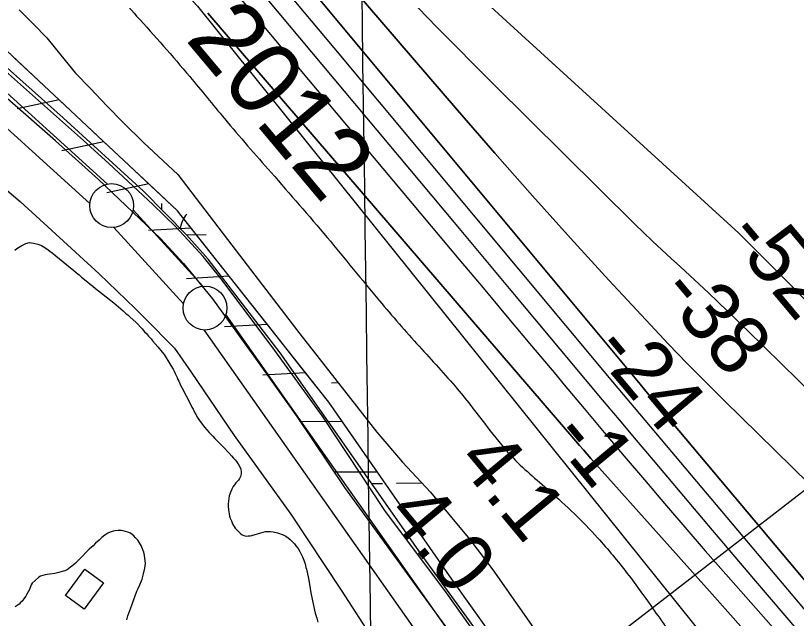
# Model space of a CAD drawing. Extents: x 3767014 to 3805179, y 361544 to 387384.
# Drawn here: x 3778598 to 3779487, y 381828 to 382515 of the extents above; entities that cross this region are included whole.
import ezdxf

# ---------------------------------------------------------------- set-up
doc = ezdxf.new("R2010")
doc.units = 0
for name, color, linetype in [('V-BLDG-OTLN', 7, 'Continuous'), ('V-FLOD-BASE', 7, 'Continuous'), ('V-GRID-MAJR', 7, 'Continuous'), ('V-LEVE-TOET', 7, 'Continuous'), ('V-RIVR-EDGE', 7, 'Continuous'), ('V-RIVR-IDEN', 7, 'Continuous'), ('V-RIVR-RANG', 7, 'Continuous'), ('V-RRAP-FSHR', 7, 'Continuous'), ('V-SITE-VEGE', 7, 'Continuous'), ('V-SURV-LINE', 7, 'Continuous'), ('V-TOPO-DPTH', 7, 'Continuous'), ('V-TOPO-MAJR', 7, 'Continuous'), ('V-TOPO-MINR', 7, 'Continuous'), ('V-TOPO-WATR', 7, 'Continuous'), ('V-WETL-SWMP', 7, 'Continuous')]:
    doc.layers.add(name, color=color, linetype=linetype)

msp = doc.modelspace()

# ---------------------------------------------------------------- linework, layer by layer
at = {"layer": 'V-BLDG-OTLN'}
msp.add_lwpolyline([(3778697.924, 381868.764), (3778675.963, 381838.749), (3778654.504, 381854.448), (3778676.467, 381884.464)], close=True, dxfattribs=at)
at = {"layer": 'V-FLOD-BASE'}
for points in [[(3778692.098, 382328.079), (3778643.187, 382372.197), (3778588.09, 382420.374), (3778515.771, 382484.163), (3778422.761, 382569.696), (3778344.896, 382643.025), (3778246.473, 382731.277)], [(3778692.098, 382328.079), (3778762.87, 382260.962), (3778789.22, 382232.479), (3778821.978, 382192.381), (3778878.031, 382114.78), (3778918.148, 382058.132), (3778972.438, 381977.367), (3779060.842, 381855.62), (3779132.377, 381757.961), (3779219.417, 381637.995), (3779266.709, 381582.32), (3779333.582, 381501.236), (3779412.295, 381404.55), (3779480.53, 381322.13), (3779548.774, 381238.814), (3779609.28, 381165.303), (3779648.831, 381119.88), (3779665.16, 381104.774), (3779773.337, 381026.358), (3779857.983, 380964.775), (3779951.271, 380892.497), (3779991.607, 380858.316), (3780033.308, 380822.351), (3780083.705, 380770.749)]]:
    msp.add_lwpolyline(points, dxfattribs=at)
at = {"layer": 'V-GRID-MAJR'}
msp.add_spline([(3779203.688, 367075.819), (3779120.863, 373133.445), (3779038.002, 379193.674), (3778955.14, 385253.903), (3778955.104, 385256.504)], degree=3, dxfattribs=at)
at = {"layer": 'V-LEVE-TOET'}
for points in [[(3778250.643, 382759.624), (3778379.499, 382638.087), (3778432.575, 382585.789), (3778534.504, 382496.902), (3778675.011, 382372.713), (3778703.947, 382346.241), (3778725.994, 382325.876)], [(3778314.358, 382577.321), (3778401.918, 382488.327), (3778454.988, 382436.713), (3778531.485, 382363.374), (3778603.096, 382303.001)], [(3778725.994, 382325.876), (3778754.088, 382299.649), (3778780.604, 382273.67), (3778811.592, 382240.57)], [(3778603.096, 382303.001), (3778693.111, 382220.604), (3778734.047, 382181.391), (3778745.423, 382169.797), (3778778.646, 382135.909), (3778797.842, 382108.634), (3778846.767, 382036.624), (3778911.184, 381947.211), (3778968.817, 381860.429), (3779005.427, 381803.607), (3779028.355, 381763.759), (3779050.305, 381731.106), (3779088.175, 381683.303), (3779173.349, 381590.048), (3779252.248, 381493.574), (3779342.061, 381386.855), (3779436.845, 381278.838)], [(3780122.202, 380758.347), (3780023.027, 380858.66), (3779982.219, 380894.594), (3779933.181, 380935.441), (3779861.303, 380988.323), (3779747.784, 381069.405), (3779669.919, 381129.952), (3779650.207, 381147.016), (3779629.983, 381169.53), (3779551.305, 381265.055), (3779458.846, 381375.434), (3779356.667, 381502.981), (3779247.187, 381633.631), (3779181.713, 381726.565), (3779088.588, 381857.385), (3779018.563, 381951.182), (3778947.489, 382058.599), (3778889.883, 382137.527), (3778830.456, 382216.891), (3778811.592, 382240.57)]]:
    msp.add_lwpolyline(points, dxfattribs=at)
at = {"layer": 'V-RIVR-EDGE'}
msp.add_spline([(3778646.24, 382647.92), (3778659.876, 382602.597), (3778687.287, 382567.754), (3778735.679, 382514.257), (3778796.164, 382445.365), (3778835.674, 382397.551), (3778888.899, 382335.956), (3778952.607, 382262.203), (3779012.275, 382190.077), (3779057.436, 382138.206), (3779100.988, 382089.574), (3779134.849, 382046.627), (3779162.264, 382013.401), (3779205.838, 381973.665), (3779260.7, 381920.153), (3779294.566, 381879.632), (3779325.194, 381837.502), (3779360.663, 381790.507), (3779412.312, 381745.899), (3779454.294, 381716.68), (3779488.994, 381685.863), (3779533.368, 381642.89), (3779576.119, 381597.495), (3779620.485, 381551.287), (3779676.969, 381499.388), (3779726.99, 381450.74), (3779776.179, 381392.389), (3779876.993, 381279.725), (3779935.05, 381210.029), (3779960.041, 381177.618), (3780000.375, 381136.273), (3780060.096, 381085.174), (3780089.114, 381046.283), (3780155.269, 380980.612), (3780221.433, 380918.984), (3780269.028, 380870.342), (3780345.672, 380794.939), (3780399.741, 380747.899), (3780525.62, 380632.747), (3780574.841, 380587.335), (3780617.604, 380546.793), (3780649.066, 380515.174), (3780673.232, 380476.295), (3780710.32, 380430.105), (3780715.929, 380409.064), (3780730.431, 380386.383), (3780746.557, 380366.934), (3780778.851, 380344.209), (3780832.137, 380307.684), (3780871.695, 380279.28), (3780938.666, 380216.842), (3780975.778, 380180.357), (3781018.547, 380142.24), (3781081.494, 380087.899), (3781142.025, 380037.607), (3781200.156, 379997.835), (3781279.276, 379942.646), (3781347.092, 379894.762), (3781401.179, 379855), (3781466.567, 379806.314), (3781540.856, 379760.032), (3781563.475, 379749.463), (3781591.761, 379741.305), (3781611.132, 379725.891), (3781641.814, 379705.597), (3781703.987, 379665.006), (3781768.578, 379621.175), (3781821.047, 379581.417), (3781840.409, 379561.959), (3781862.209, 379547.348), (3781884.029, 379540.824), (3781913.115, 379529.43), (3781965.635, 379509.89), (3782018.949, 379484.687), (3782023.776, 379474.162), (3782024.562, 379465.264), (3782031.018, 379459.587), (3782040.723, 379459.563), (3782056.888, 379455.479), (3782096.48, 379440.824), (3782142.534, 379422.918), (3782192.615, 379398.532), (3782256.437, 379370.877), (3782308.124, 379341.634), (3782355.768, 379312.402), (3782425.225, 379274.219), (3782483.37, 379240.108), (3782518.081, 379214.143), (3782612.541, 379148.401), (3782677.126, 379102.144), (3782722.345, 379073.726), (3782774.821, 379036.394), (3782813.562, 379004.757), (3782852.3, 378971.503), (3782891.856, 378942.291), (3782929.816, 378921.979), (3782948.387, 378909.802), (3782956.456, 378902.503), (3782965.324, 378891.159), (3782976.623, 378881.426), (3783009.747, 378867.595), (3783020.246, 378861.908), (3783062.243, 378838.351), (3783100.998, 378812.375), (3783151.876, 378783.135), (3783202.741, 378748.233), (3783247.956, 378718.198), (3783325.482, 378672.717), (3783407.843, 378619.945), (3783473.245, 378576.92), (3783515.225, 378546.893), (3783550.759, 378526.587), (3783593.566, 378503.836), (3783636.355, 378473.807), (3783701.749, 378427.547), (3783745.35, 378399.134), (3783781.695, 378379.634), (3783840.643, 378343.095), (3783916.53, 378288.722), (3783971.442, 378255.428), (3784058.669, 378208.305), (3784177.383, 378139.269), (3784249.255, 378096.228), (3784300.952, 378071.029), (3784367.999, 378039.322), (3784407.569, 378015.771), (3784474.592, 377974.36), (3784555.345, 377925.636), (3784594.113, 377904.513), (3784636.123, 377886.616), (3784690.236, 377857.368), (3784719.292, 377833.843), (3784772.601, 377806.214), (3784811.368, 377785.091), (3784863.85, 377750.185), (3784995.456, 377661.707), (3785050.364, 377626.795), (3785102.863, 377599.168), (3785153.772, 377582.059), (3785203.053, 377560.91), (3785266.865, 377529.211)], degree=3, dxfattribs=at)
at = {"layer": 'V-RIVR-RANG'}
msp.add_line((3779154.354, 381710.227), (3779787.615, 382199.083), dxfattribs=at)
at = {"layer": 'V-RRAP-FSHR'}
for p, q in [((3778647.232, 382418.815), (3778599.451, 382408.741)), ((3778698.347, 382370.991), (3778650.567, 382360.917)), ((3778749.462, 382323.168), (3778701.682, 382313.094)), ((3778797.832, 382272.817), (3778749.084, 382269.974)), ((3778841.251, 382217.912), (3778792.503, 382215.069)), ((3778884.671, 382163.007), (3778835.923, 382160.164)), ((3778928.09, 382108.101), (3778879.342, 382105.258)), ((3778970.17, 382052.202), (3778921.34, 382052.369)), ((3779010.123, 381994.725), (3778961.293, 381994.892))]:
    msp.add_line(p, q, dxfattribs=at)
for points in [[(3782184.756, 379271.949), (3781634.784, 379600.702), (3781303.145, 379780.78), (3781133.821, 379909.411), (3780890.404, 380113.256), (3780565.67, 380378.863), (3780204.676, 380695.617), (3779970.329, 380928.932), (3779684.372, 381135.741), (3779561.421, 381256.633), (3779323.818, 381551.992), (3779094.739, 381872.997), (3778954.725, 382074.421), (3778782.34, 382292.407), (3778544.366, 382515.056), (3778048.414, 382973.145), (3777558.565, 383445.969), (3777072.653, 383926.093), (3776661.747, 384415.936), (3776254.152, 384895.528), (3775977.183, 385214.815)], [(3777068.879, 384385.699), (3778804.838, 382525.57), (3779492.47, 381669.823), (3779587.876, 381548.643), (3779796.903, 381343.309), (3779998.867, 381129.354), (3780179.181, 380943.203), (3780223.637, 380900.07), (3780597.798, 380548.597), (3780675.78, 380460.512), (3780749.105, 380378.076), (3780977.321, 380170.04), (3781125.621, 380046.136), (3781247.143, 379955.707), (3781372.841, 379865.857), (3781588.295, 379714.948), (3781871.171, 379550.27), (3782261.845, 379357.404), (3782506.653, 379202.456), (3782967.84, 378875.243), (3783363.457, 378614.539), (3783723.393, 378389.37)], [(3778647.232, 382418.815), (3778596.116, 382466.639)], [(3778698.347, 382370.991), (3778647.231, 382418.815)], [(3778749.462, 382323.168), (3778698.346, 382370.992)], [(3778797.832, 382272.817), (3778782.34, 382292.407), (3778749.461, 382323.168)], [(3778841.251, 382217.912), (3778797.831, 382272.818)], [(3778884.671, 382163.007), (3778841.251, 382217.913)], [(3778928.09, 382108.101), (3778884.67, 382163.007)], [(3778970.17, 382052.202), (3778954.725, 382074.421), (3778928.09, 382108.102)], [(3779010.123, 381994.725), (3778970.17, 382052.203)], [(3779020.217, 381980.205), (3779010.123, 381994.726)]]:
    msp.add_lwpolyline(points, dxfattribs=at)
at = {"layer": 'V-SITE-VEGE'}
for points in [[(3778596.827, 382247.474), (3778599.034, 382249.407), (3778602.825, 382251.99), (3778604.881, 382253.124), (3778609.317, 382255.078), (3778613.759, 382256.237), (3778618.22, 382255.807), (3778623.004, 382254.583), (3778625.398, 382253.813), (3778627.317, 382252.877), (3778629.236, 382251.783), (3778633.24, 382249.278), (3778636.769, 382246.45), (3778639.493, 382244.57), (3778656.178, 382231.057), (3778664.2, 382224.459), (3778667.089, 382221.784), (3778670.137, 382219.429), (3778672.867, 382216.912), (3778680.084, 382211.257), (3778682.814, 382208.9), (3778685.7, 382206.7), (3778688.747, 382204.185), (3778709.6, 382187.695), (3778720.352, 382178.577), (3778723.885, 382175.274), (3778725.648, 382174.02), (3778727.899, 382171.815), (3778735.122, 382165.366), (3778742.038, 382158.118), (3778744.776, 382154.804), (3778746.865, 382152.758), (3778749.284, 382149.76), (3778752.182, 382146.608), (3778753.789, 382144.396), (3778759.907, 382137.617), (3778764.9, 382131.623), (3778766.837, 382128.78), (3778773.469, 382118.348), (3778774.441, 382116.447), (3778777.192, 382112.023), (3778778.329, 382109.805), (3778779.469, 382107.112), (3778781.743, 382102.523), (3778782.56, 382100.462), (3778783.692, 382098.566)], [(3778783.692, 382098.566), (3778785.974, 382093.337), (3778787.436, 382090.331), (3778796.683, 382072.925), (3778798.473, 382068.966), (3778799.931, 382066.435), (3778802.204, 382061.845), (3778803.337, 382060.107), (3778804.795, 382057.575), (3778808.027, 382052.676), (3778813.024, 382046.205), (3778818.176, 382040.212), (3778822.516, 382035.803), (3778824.769, 382033.28), (3778827.177, 382031.076), (3778830.235, 382027.769), (3778834.898, 382023.042), (3778840.85, 382016.74), (3778843.746, 382013.586), (3778846.16, 382010.748), (3778848.09, 382008.7), (3778850.346, 382005.859), (3778852.126, 382003.014), (3778853.427, 382000.321)], [(3778853.427, 382000.321), (3778854.404, 381998.105), (3778854.907, 381995.406), (3778854.774, 381992.861), (3778853.851, 381989.985), (3778852.921, 381987.591), (3778851.823, 381985.83), (3778848.833, 381982.616), (3778847.107, 381980.53), (3778845.695, 381978.449), (3778843.975, 381975.565), (3778843.049, 381972.694), (3778841.188, 381968.061), (3778840.295, 381962.005), (3778840.01, 381958.821), (3778840.043, 381955.64), (3778840.233, 381952.46), (3778841.585, 381944.677), (3778842.245, 381942.617), (3778843.549, 381939.289), (3778845.016, 381935.963), (3778847.768, 381931.218), (3778850.826, 381927.908), (3778853.877, 381925.076), (3778855.96, 381923.667), (3778857.877, 381922.891), (3778860.271, 381922.118), (3778862.817, 381922.463), (3778864.883, 381922.325), (3778866.948, 381922.663), (3778877.255, 381925.952), (3778882.334, 381927.118), (3778884.878, 381927.302), (3778887.741, 381927.333), (3778891.083, 381927.048), (3778896.029, 381925.825), (3778902.734, 381923.667), (3778905.618, 381921.787), (3778908.182, 381919.905), (3778910.429, 381918.018), (3778915.409, 381913.138), (3778917.181, 381911.088), (3778919.6, 381907.932), (3778921.703, 381904.61), (3778924.629, 381898.278), (3778926.1, 381894.632), (3778927.575, 381890.352), (3778928.572, 381886.225), (3778929.227, 381884.323), (3778931.226, 381875.594), (3778931.904, 381871.623), (3778932.422, 381867.492), (3778934.114, 381857.488), (3778936.969, 381843.037), (3778939.123, 381834.468), (3778940.932, 381828.76), (3778942.255, 381824.001)], [(3778724.427, 381826.704), (3778725.654, 381831.171), (3778730.141, 381843.467), (3778730.913, 381845.863), (3778736.025, 381859.28), (3778737.117, 381861.516), (3778739.292, 381866.63), (3778741.772, 381873.02), (3778743.617, 381879.242), (3778744.983, 381885.621), (3778745.434, 381888.331), (3778745.567, 381890.876), (3778745.372, 381894.374), (3778744.52, 381899.775), (3778743.685, 381903.906), (3778742.861, 381906.441), (3778741.071, 381910.4), (3778738.966, 381914.197), (3778736.865, 381917.357), (3778734.448, 381920.195), (3778732.519, 381922.245), (3778731.073, 381923.661), (3778728.507, 381925.545), (3778725.793, 381926.47), (3778722.922, 381927.236), (3778720.208, 381928.162), (3778718.138, 381928.301), (3778714.316, 381928.58), (3778711.14, 381928.23), (3778708.918, 381927.73), (3778705.588, 381926.581), (3778702.737, 381925.281), (3778699.579, 381923.179), (3778695.946, 381920.437), (3778692.794, 381917.541), (3778688.694, 381914), (3778686.017, 381911.108), (3778681.763, 381907.088), (3778670.11, 381895.355), (3778665.856, 381891.335), (3778663.02, 381888.761), (3778660.337, 381886.506), (3778656.389, 381883.759), (3778653.695, 381882.619), (3778651.793, 381881.963), (3778647.193, 381880.642), (3778642.274, 381879.479), (3778636.713, 381878.627), (3778633.693, 381878.439), (3778631.469, 381878.097), (3778626.238, 381876.292), (3778624.18, 381875.156), (3778619.922, 381871.615), (3778616.772, 381868.399), (3778615.359, 381866.636), (3778613.61, 381861.066)], [(3778613.61, 381861.066), (3778610.513, 381855.784), (3778609.485, 381853.672), (3778607.929, 381851.821), (3778605.082, 381847.854), (3778603.524, 381846.263), (3778601.703, 381844.667), (3778599.62, 381843.072), (3778597.271, 381841.472)]]:
    msp.add_lwpolyline(points, dxfattribs=at)
at = {"layer": 'V-SURV-LINE'}
for points in [[(3778143.366, 382830.007), (3778702.45, 382322.94)], [(3778682.288, 382300.726), (3778123.204, 382807.792)], [(3778731.723, 382293.74), (3778811.15, 382206.594)], [(3778788.982, 382186.381), (3778709.554, 382273.527)], [(3778837.291, 382174.017), (3779169.048, 381702.633)], [(3779144.516, 381685.364), (3778812.759, 382156.75)]]:
    msp.add_lwpolyline(points, dxfattribs=at)
for centre in [(3778707.175, 382298.405), (3778813.53, 382181.716)]:
    msp.add_circle(centre, 25, dxfattribs=at)
at = {"layer": 'V-TOPO-DPTH'}
for points in [[(3780033.44, 381447.279), (3779909.446, 381577.894), (3779904.885, 381582.669), (3779900.304, 381587.425), (3779895.694, 381592.152), (3779891.063, 381596.86), (3779845.629, 381642.766), (3779818.205, 381670.35), (3779790.697, 381697.851), (3779763.065, 381725.227), (3779735.35, 381752.519), (3779404.858, 382076.499), (3779383.577, 382097.655), (3779362.498, 382119.007), (3779341.72, 382140.652), (3779321.143, 382162.494), (3779273.749, 382213.512), (3779229.91, 382261.263), (3779186.451, 382309.353), (3779143.559, 382357.95), (3779101.046, 382406.885), (3778795.842, 382762.398)], [(3780033.44, 381447.279), (3779909.446, 381577.894), (3779904.885, 381582.669), (3779900.304, 381587.425), (3779895.694, 381592.152), (3779891.063, 381596.86), (3779845.629, 381642.766), (3779818.205, 381670.35), (3779790.697, 381697.851), (3779763.065, 381725.227), (3779735.35, 381752.519), (3779404.858, 382076.499), (3779383.577, 382097.655), (3779362.498, 382119.007), (3779341.72, 382140.652), (3779321.143, 382162.494), (3779273.749, 382213.512), (3779229.91, 382261.263), (3779186.451, 382309.353), (3779143.559, 382357.95), (3779101.046, 382406.885), (3778795.842, 382762.398)], [(3778720.082, 382730.103), (3778909.421, 382503.635), (3778972.04, 382428.742), (3779034.665, 382353.854), (3779097.296, 382278.972), (3779159.933, 382204.095), (3779246.656, 382100.433), (3779265.952, 382077.403), (3779285.271, 382054.393), (3779304.623, 382031.411), (3779323.999, 382008.449), (3779387.171, 381933.693), (3779438.344, 381873.534), (3779489.775, 381813.599), (3779541.593, 381753.998), (3779593.67, 381694.62), (3779748.837, 381518.851), (3779764.073, 381501.736), (3779779.401, 381484.707), (3779794.87, 381467.804), (3779810.433, 381450.987), (3780144.803, 381092.655)], [(3778720.082, 382730.103), (3778909.421, 382503.635), (3778972.04, 382428.742), (3779034.665, 382353.854), (3779097.296, 382278.972), (3779159.933, 382204.095), (3779246.656, 382100.433), (3779265.952, 382077.403), (3779285.271, 382054.393), (3779304.623, 382031.411), (3779323.999, 382008.449), (3779387.171, 381933.693), (3779438.344, 381873.534), (3779489.775, 381813.599), (3779541.593, 381753.998), (3779593.67, 381694.62), (3779748.837, 381518.851), (3779764.073, 381501.736), (3779779.401, 381484.707), (3779794.87, 381467.804), (3779810.433, 381450.987), (3780144.803, 381092.655)], [(3780425.097, 380890.853), (3779950.523, 381358.07), (3779925.981, 381382.495), (3779901.617, 381407.093), (3779877.52, 381431.954), (3779853.601, 381456.989), (3779813.295, 381499.634), (3779809.684, 381503.497), (3779806.1, 381507.385), (3779802.559, 381511.312), (3779799.046, 381515.264), (3779773.24, 381544.609), (3779756.908, 381563.307), (3779740.659, 381582.076), (3779724.534, 381600.952), (3779708.492, 381619.9), (3779329.372, 382070.73), (3779324.309, 382076.759), (3779319.252, 382082.794), (3779314.203, 382088.835), (3779309.16, 382094.881), (3778809.915, 382694.298)], [(3778809.915, 382694.298), (3779309.16, 382094.881), (3779314.203, 382088.835), (3779319.252, 382082.794), (3779324.309, 382076.759), (3779329.372, 382070.73), (3779708.492, 381619.9), (3779724.534, 381600.952), (3779740.659, 381582.076), (3779756.908, 381563.307), (3779773.24, 381544.609), (3779799.046, 381515.264), (3779802.559, 381511.312), (3779806.1, 381507.385), (3779809.684, 381503.497), (3779813.295, 381499.634), (3779853.601, 381456.989), (3779877.52, 381431.954), (3779901.617, 381407.093), (3779925.981, 381382.495), (3779950.523, 381358.07), (3780425.097, 380890.853)], [(3779014.051, 382567.625), (3779077.624, 382501.642), (3779142.118, 382436.529), (3779302.652, 382277.781), (3779312.986, 382267.712), (3779323.418, 382257.747), (3779333.995, 382247.937), (3779344.67, 382238.23), (3779355.371, 382228.551), (3779366.009, 382218.803), (3779376.553, 382208.953), (3779387.033, 382199.035), (3779408.757, 382178.277), (3779414.518, 382172.752), (3779420.265, 382167.212), (3779425.991, 382161.651), (3779431.703, 382156.076), (3779683.405, 381909.478)], [(3779014.051, 382567.625), (3779077.624, 382501.642), (3779142.118, 382436.529), (3779302.652, 382277.781), (3779312.986, 382267.712), (3779323.418, 382257.747), (3779333.995, 382247.937), (3779344.67, 382238.23), (3779355.371, 382228.551), (3779366.009, 382218.803), (3779376.553, 382208.953), (3779387.033, 382199.035), (3779408.757, 382178.277), (3779414.518, 382172.752), (3779420.265, 382167.212), (3779425.991, 382161.651), (3779431.703, 382156.076), (3779683.405, 381909.478)], [(3780333.924, 380820.866), (3779911.357, 381273.602), (3779883.463, 381303.744), (3779855.742, 381334.042), (3779828.281, 381364.576), (3779800.992, 381395.267), (3779754.306, 381448.226), (3779750.487, 381452.552), (3779746.664, 381456.874), (3779742.834, 381461.19), (3779739.001, 381465.503), (3779627.201, 381591.093), (3779567.454, 381658.19), (3779507.695, 381725.274), (3779447.915, 381792.341), (3779388.122, 381859.397), (3779253.26, 382010.596), (3779248.919, 382015.489), (3779244.595, 382020.398), (3779240.297, 382025.33), (3779236.017, 382030.277), (3778816.638, 382517.638)]]:
    msp.add_lwpolyline(points, dxfattribs=at)
at = {"layer": 'V-TOPO-MAJR'}
msp.add_lwpolyline([(3778939.473, 382707.222), (3779421.519, 382267.07), (3779448.526, 382240.229), (3779475.436, 382213.292), (3779502.2, 382186.21), (3779528.867, 382159.031), (3779555.481, 382131.799), (3779582.121, 382104.594), (3779608.801, 382077.427), (3779635.508, 382050.286), (3779969.169, 381711.685), (3779986.824, 381693.825), (3780004.517, 381676.002), (3780022.265, 381658.236), (3780040.052, 381640.506)], dxfattribs=at)
at = {"layer": 'V-TOPO-MINR'}
for points in [[(3778795.842, 382762.398), (3779101.046, 382406.885), (3779143.559, 382357.95), (3779186.451, 382309.353), (3779229.91, 382261.263), (3779273.749, 382213.512), (3779321.143, 382162.494), (3779341.72, 382140.652), (3779362.498, 382119.007), (3779383.577, 382097.655), (3779404.858, 382076.499), (3779735.35, 381752.519), (3779763.065, 381725.227), (3779790.697, 381697.851), (3779818.205, 381670.35), (3779845.629, 381642.766), (3779891.063, 381596.86), (3779895.694, 381592.152), (3779900.304, 381587.425), (3779904.885, 381582.669), (3779909.446, 381577.894), (3780033.44, 381447.279)], [(3778720.082, 382730.103), (3778909.421, 382503.635), (3778972.04, 382428.742), (3779034.665, 382353.854), (3779097.296, 382278.972), (3779159.933, 382204.095), (3779246.656, 382100.433), (3779265.952, 382077.403), (3779285.271, 382054.393), (3779304.623, 382031.411), (3779323.999, 382008.449), (3779387.171, 381933.693), (3779438.344, 381873.534), (3779489.775, 381813.599), (3779541.593, 381753.998), (3779593.67, 381694.62), (3779748.837, 381518.851), (3779764.073, 381501.736), (3779779.401, 381484.707), (3779794.87, 381467.804), (3779810.433, 381450.987), (3780144.803, 381092.655)], [(3778716.925, 382697.962), (3779102.687, 382237.579), (3779130.268, 382204.666), (3779157.85, 382171.754), (3779185.436, 382138.845), (3779213.023, 382105.938), (3779222.649, 382094.456), (3779245.446, 382067.308), (3779268.27, 382040.184), (3779291.136, 382013.095), (3779314.03, 381986.029), (3779337.026, 381959.051), (3779360.131, 381932.168), (3779383.399, 381905.425), (3779406.776, 381878.777), (3779722.81, 381520.722), (3779744.093, 381496.752), (3779765.47, 381472.867), (3779786.989, 381449.109), (3779808.601, 381425.436), (3780193.458, 381006.379)], [(3778809.915, 382694.298), (3779309.16, 382094.881), (3779314.203, 382088.835), (3779319.252, 382082.794), (3779324.309, 382076.759), (3779329.372, 382070.73), (3779708.492, 381619.9), (3779724.534, 381600.952), (3779740.659, 381582.076), (3779756.908, 381563.307), (3779773.24, 381544.609), (3779799.046, 381515.264), (3779802.559, 381511.312), (3779806.1, 381507.385), (3779809.684, 381503.497), (3779813.295, 381499.634), (3779853.601, 381456.989), (3779877.52, 381431.954), (3779901.617, 381407.093), (3779925.981, 381382.495), (3779950.523, 381358.07), (3780425.097, 380890.853)], [(3779014.051, 382567.625), (3779077.624, 382501.642), (3779142.118, 382436.529), (3779302.652, 382277.781), (3779312.986, 382267.712), (3779323.418, 382257.747), (3779333.995, 382247.937), (3779344.67, 382238.23), (3779355.371, 382228.551), (3779366.009, 382218.803), (3779376.553, 382208.953), (3779387.033, 382199.035), (3779408.757, 382178.277), (3779414.518, 382172.752), (3779420.265, 382167.212), (3779425.991, 382161.651), (3779431.703, 382156.076), (3779683.405, 381909.478)], [(3778908.814, 382539.875), (3778960.396, 382478.067), (3779011.982, 382416.263), (3779277.929, 382097.672), (3779290.089, 382083.127), (3779302.262, 382068.594), (3779314.457, 382054.078), (3779326.665, 382039.574), (3779529.863, 381798.528), (3779573.082, 381747.6), (3779616.521, 381696.861), (3779660.292, 381646.409), (3779704.284, 381596.147), (3779773.956, 381517.069), (3779783.328, 381506.534), (3779792.766, 381496.06), (3779802.304, 381485.677), (3779811.909, 381475.354), (3779924.241, 381355.777), (3779990.452, 381286.092), (3780057.183, 381216.914)]]:
    msp.add_lwpolyline(points, dxfattribs=at)
at = {"layer": 'V-TOPO-WATR'}
msp.add_lwpolyline([(3778816.638, 382517.638), (3779236.017, 382030.277), (3779240.297, 382025.33), (3779244.595, 382020.398), (3779248.919, 382015.489), (3779253.26, 382010.596), (3779388.122, 381859.397), (3779447.915, 381792.341), (3779507.695, 381725.274), (3779567.454, 381658.19), (3779627.201, 381591.093), (3779739.001, 381465.503), (3779742.834, 381461.19), (3779746.664, 381456.874), (3779750.487, 381452.552), (3779754.306, 381448.226), (3779800.992, 381395.267), (3779828.281, 381364.576), (3779855.742, 381334.042), (3779883.463, 381303.744), (3779911.357, 381273.602), (3780333.924, 380820.866)], dxfattribs=at)
at = {"layer": 'V-WETL-SWMP'}
for p, q in [((3778764.274, 382293.9), (3778764.177, 382300.877)), ((3778792.351, 382265.265), (3778814.673, 382265.575)), ((3778957.505, 382096.732), (3778965.312, 382096.84)), ((3779003.358, 381981.926), (3779015.697, 381982.098)), ((3779031.695, 381982.32), (3779060.545, 381982.721))]:
    msp.add_line(p, q, dxfattribs=at)
for points in [[(3778743.573, 382315.008), (3778651.948, 382398.499), (3778517.632, 382517.941)], [(3778601.774, 382521.299), (3778618.317, 382504.998), (3778633.486, 382489.372), (3778649.37, 382469.645), (3778665.943, 382449.239), (3778683.181, 382431.575), (3778701.802, 382411.868), (3778720.417, 382392.845), (3778743.853, 382369.753), (3778782.438, 382333.771), (3778844, 382253.281), (3778921.389, 382152.423), (3778972.639, 382087.566), (3779009.393, 382040.219), (3779038.614, 382006.157), (3779070.459, 381972.122), (3779115.155, 381918.175), (3779141.518, 381883.606), (3779221.668, 381769.413), (3779330.089, 381620.671), (3779423.953, 381495.404), (3779516.298, 381378.711), (3779582.297, 381294.916)], [(3780170.724, 380719.763), (3780021.855, 380864.843), (3779959.537, 380918.547), (3779916.944, 380954.859), (3779827.937, 381018.845), (3779698.328, 381115.646), (3779664.45, 381140.71), (3779636.417, 381167.789), (3779568.737, 381248.804), (3779491.54, 381343.013), (3779428.184, 381421.726), (3779292.418, 381585.314), (3779229.043, 381665.982), (3779216.757, 381682.275), (3779169.935, 381749.82), (3779061.684, 381898.834), (3778899.028, 382130.562), (3778817.012, 382237.232), (3778792.489, 382265.129), (3778743.573, 382315.008)]]:
    msp.add_lwpolyline(points, dxfattribs=at)
msp.add_arc((3778819.908, 382266.123), 35.246, 140.024032, 169.557422, dxfattribs=at)

# ---------------------------------------------------------------- texts
at = {"layer": 'V-RIVR-IDEN'}
msp.add_text(' 2012', height=83, rotation=309.98913, dxfattribs=at).set_placement((3778770.326, 382511.338))
at = {"layer": 'V-RIVR-RANG'}
for s, rotation, p in [('-52', 310.031028, (3779405.68, 382263.214)), ('-38', 310.031028, (3779329.29, 382198.679)), ('-24', 310.031028, (3779253.411, 382133.539)), ('-1', 309.748326, (3779206.232, 382034.503)), ('4.1', 309.748326, (3779098.975, 382007.081)), ('4.0', 309.748326, (3779018.873, 381947.006))]:
    msp.add_text(s, height=67, rotation=rotation, dxfattribs=at).set_placement(p)

doc.saveas('drawing.dxf')
